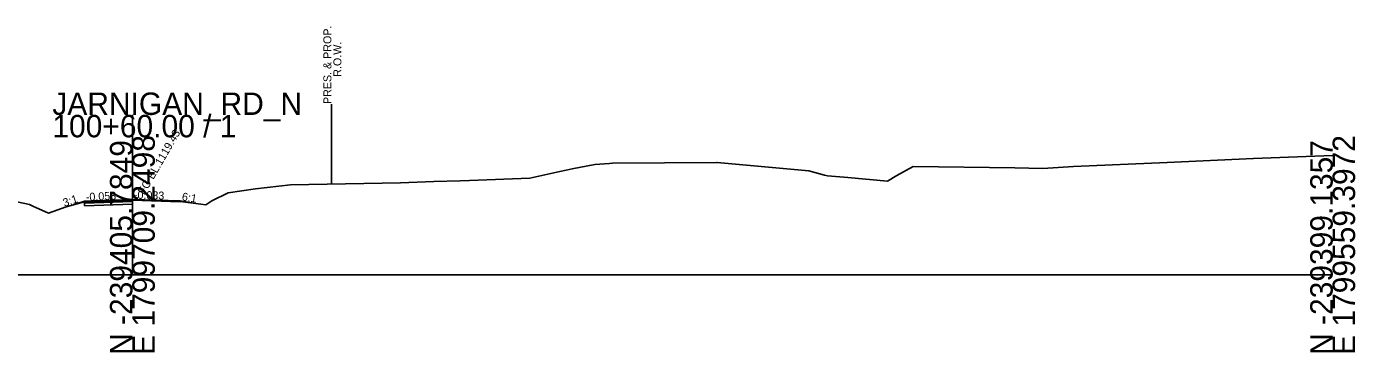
# Model space of a CAD drawing. Extents: x 214513 to 217151, y 214739 to 216780.
# Drawn here: x 214885.1 to 215051.2, y 215238.7 to 215279.4 of the extents above; entities that cross this region are included whole.
import ezdxf

# ---------------------------------------------------------------- set-up
doc = ezdxf.new("R2010")
doc.units = 0
for name, color, linetype in [('CONCEPT - TRANSPORTATION - Roads Text', 7, 'Continuous'), ('DESIGN - CENTERLINE - Proposed Text', 7, 'Continuous'), ('DESIGN - DRAINAGE - Special Ditches', 7, 'Continuous'), ('DESIGN - EARTHWORK - Shapes', 7, 'Continuous'), ('DESIGN - TRANSPORTATION - Text', 7, 'Continuous'), ('DESIGN - TYPICAL - Slope Tie Text', 7, 'Continuous'), ('SURVEY - DTM GRAPHICS - Triangles', 7, 'Continuous'), ('SURVEY - PROPERTY - ROW Lines', 7, 'Continuous'), ('XSCell', 7, 'Continuous')]:
    doc.layers.add(name, color=color, linetype=linetype)

msp = doc.modelspace()

# ---------------------------------------------------------------- linework, layer by layer
at = {"layer": 'DESIGN - DRAINAGE - Special Ditches'}
for points in [[(214892.39, 215257.58), (214891.23, 215257.19)], [(214892.39, 215257.58), (214898.36, 215257.79), (214898.36, 215257.69), (214898.36, 215257.69), (214892.39, 215257.48), (214892.39, 215257.48), (214892.39, 215257.48), (214892.39, 215257.58), (214892.39, 215257.58)], [(214892.39, 215257.48), (214898.36, 215257.69), (214898.36, 215257.54), (214898.36, 215257.54), (214892.39, 215257.33), (214892.39, 215257.33), (214892.39, 215257.33), (214892.39, 215257.48), (214892.39, 215257.48)], [(214892.39, 215257.33), (214892.39, 215257.33), (214892.39, 215257), (214892.39, 215257), (214892.39, 215257), (214898.36, 215257.21), (214898.36, 215257.21), (214898.36, 215257.54), (214892.39, 215257.33)], [(214898.36, 215257.79), (214898.36, 215257.79), (214898.36, 215257.69), (214898.36, 215257.69), (214898.36, 215257.69), (214904.33, 215257.5), (214904.33, 215257.5), (214904.33, 215257.6), (214898.36, 215257.79)], [(214904.33, 215257.6), (214905.79, 215257.36)]]:
    msp.add_lwpolyline(points, dxfattribs=at)
at = {"layer": 'DESIGN - EARTHWORK - Shapes'}
for p, q in [((214892.39, 215257.58), (214891.23, 215257.19)), ((214892.39, 215257.48), (214898.36, 215257.69)), ((214892.39, 215257.51), (214892.39, 215257.58)), ((214898.36, 215257.54), (214892.39, 215257.33)), ((214892.39, 215257.33), (214898.36, 215257.54)), ((214892.39, 215257.51), (214892.39, 215257.48)), ((214892.39, 215257.51), (214892.39, 215257.51)), ((214898.36, 215257.69), (214898.36, 215257.71)), ((214904.33, 215257.6), (214904.33, 215257.53)), ((214905.79, 215257.36), (214904.33, 215257.6)), ((214904.33, 215257.53), (214905.79, 215257.36)), ((214904.33, 215257.5), (214904.33, 215257.53))]:
    msp.add_line(p, q, dxfattribs=at)
for points in [[(214891.23, 215257.19), (214892.39, 215257.51), (214892.39, 215257.51)], [(214898.36, 215257.71), (214898.32, 215257.7), (214892.39, 215257.51)], [(214898.36, 215257.54), (214898.36, 215257.69), (214892.39, 215257.48), (214892.39, 215257.33)], [(214892.39, 215257.33), (214892.39, 215257), (214898.36, 215257.21), (214898.36, 215257.54)], [(214904.33, 215257.53), (214899.15, 215257.7), (214898.79, 215257.72), (214898.36, 215257.71)], [(214898.36, 215257.71), (214898.36, 215257.69), (214904.33, 215257.5)]]:
    msp.add_lwpolyline(points, dxfattribs=at)
at = {"layer": 'SURVEY - DTM GRAPHICS - Triangles'}
msp.add_lwpolyline([(214881.98, 215257.92), (214885.51, 215257.15), (214885.92, 215256.96), (214887.88, 215256.07), (214890.08, 215256.88), (214892.39, 215257.51), (214898.32, 215257.7), (214898.79, 215257.72), (214899.15, 215257.7), (214904.33, 215257.53), (214906.93, 215257.22), (214907.56, 215257.14), (214908.31, 215257.6), (214910.35, 215258.64), (214913.75, 215259.13), (214918.13, 215259.63), (214931.88, 215259.86), (214936.04, 215260.02), (214939.34, 215260.14), (214940.49, 215260.18), (214948.04, 215260.46), (214951.78, 215261.27), (214952.58, 215261.44), (214953.34, 215261.6), (214956.14, 215262.15), (214957.98, 215262.3), (214958.37, 215262.34), (214971.35, 215262.41), (214971.39, 215262.41), (214971.44, 215262.4), (214982.91, 215261.39), (214984.84, 215260.83), (214985.24, 215260.74), (214987.78, 215260.53), (214992.72, 215260.08), (214993.88, 215260.79), (214995.95, 215261.93), (215008.63, 215261.74), (215012.14, 215261.65), (215015.96, 215261.93), (215027.68, 215262.43), (215038.47, 215262.93), (215048.36, 215263.27)], dxfattribs=at)
at = {"layer": 'SURVEY - PROPERTY - ROW Lines'}
msp.add_lwpolyline([(214923.23, 215269.72), (214923.23, 215259.72)], dxfattribs=at)
at = {"layer": 'XSCell'}
for p, q in [((214898.36, 215248.36), (214898.36, 215268.36)), ((214748.36, 215248.36), (214898.36, 215248.36)), ((214898.36, 215248.36), (215048.36, 215248.36))]:
    msp.add_line(p, q, dxfattribs=at)

# ---------------------------------------------------------------- texts
at = {"layer": 'CONCEPT - TRANSPORTATION - Roads Text'}
for s, rotation, p in [('-0.033', 358.1289, (214898.54, 215257.89)), ('-0.053', 3.0169, (214892.57, 215257.59))]:
    msp.add_text(s, height=1, rotation=rotation, dxfattribs=at).set_placement(p)
at = {"layer": 'DESIGN - CENTERLINE - Proposed Text'}
msp.add_text('FG EL.1119.43', height=1, rotation=60, dxfattribs=at).set_placement((214899.86, 215258.29))
at = {"layer": 'DESIGN - TRANSPORTATION - Text'}
for s, p in [('PRES. & PROP. ', (214923.23, 215269.72)), ('R.O.W.', (214924.48, 215273.13))]:
    msp.add_text(s, height=1, rotation=90, dxfattribs=at).set_placement(p)
at = {"layer": 'DESIGN - TYPICAL - Slope Tie Text'}
for s, rotation, p in [('3:1', 18.4349, (214889.87, 215256.87)), ('6:1', 350.5377, (214904.49, 215257.69))]:
    msp.add_text(s, height=1, rotation=rotation, dxfattribs=at).set_placement(p)
at = {"layer": 'XSCell'}
for s, p in [('JARNIGAN_RD_N', (214888.36, 215268.36)), ('100+60.00 / 1', (214888.36, 215265.56))]:
    msp.add_text(s, height=2.8, dxfattribs=at).set_placement(p)
for s, p in [('E 1799709.2498', (214901.16, 215238.36)), ('E 1799559.3972', (215051.16, 215238.36)), ('N -239405.7849', (214898.36, 215238.36)), ('N -239399.1357', (215048.36, 215238.36))]:
    msp.add_text(s, height=2.8, rotation=90, dxfattribs=at).set_placement(p)

doc.saveas('drawing.dxf')
